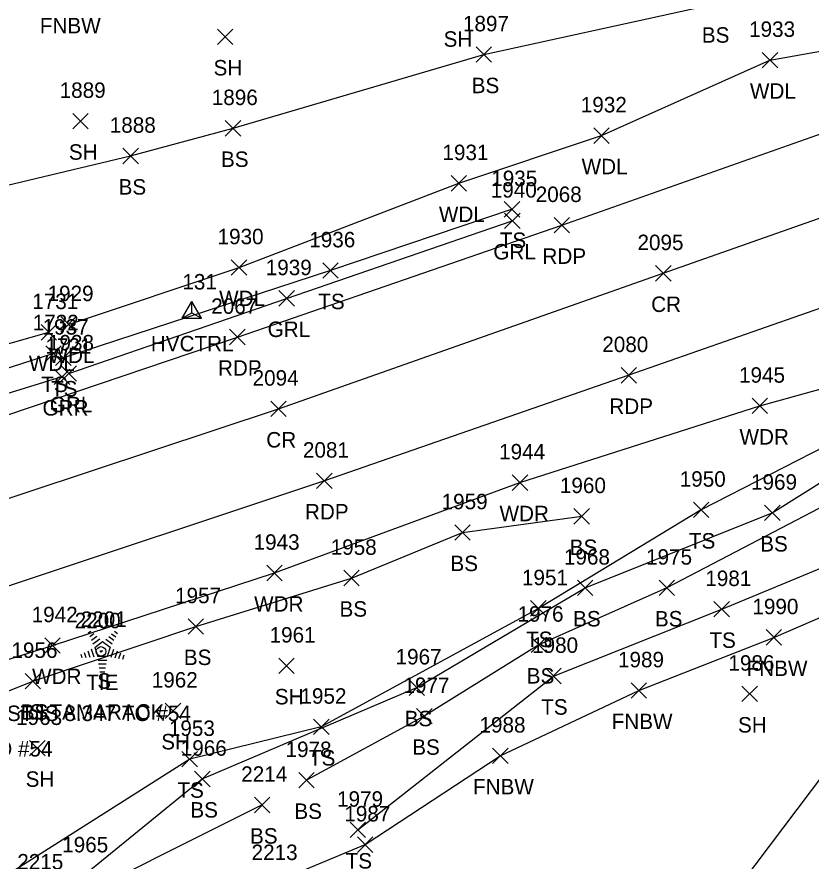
# Model space of a CAD drawing. Extents: x 1526508 to 1531550, y 369926 to 373082.
# Drawn here: x 1531231.6 to 1531334.3, y 370143.1 to 370252.3 of the extents above; entities that cross this region are included whole.
import ezdxf

# ---------------------------------------------------------------- set-up
doc = ezdxf.new("R2010")
doc.units = 0
for name, color, linetype in [('C_A', 7, 'Continuous'), ('C_C', 7, 'Continuous'), ('C_I', 7, 'Continuous'), ('CBP', 7, 'Continuous'), ('CPSM', 7, 'Continuous'), ('L_A', 7, 'Continuous'), ('L_C', 7, 'Continuous'), ('L_I', 7, 'Continuous'), ('L_TIC', 7, 'Continuous'), ('LAWA', 7, 'Continuous'), ('LELB', 7, 'Continuous'), ('LFNC', 7, 'Continuous'), ('LSOGP', 7, 'Continuous'), ('LTC', 7, 'Continuous'), ('P_A', 7, 'Continuous'), ('P_I', 7, 'Continuous'), ('P_TIC', 7, 'Continuous'), ('PET', 7, 'Continuous'), ('PRC', 7, 'Continuous'), ('R_A', 7, 'Continuous'), ('R_I', 7, 'Continuous'), ('R_TIC', 7, 'Continuous'), ('RGR', 7, 'Continuous')]:
    doc.layers.add(name, color=color, linetype=linetype)

msp = doc.modelspace()

# ---------------------------------------------------------------- linework, layer by layer
at = {"layer": 'CBP'}
for radius in [0.625, 0.0833]:
    msp.add_circle((1531242.44, 370170.23), radius, dxfattribs=at)
at = {"layer": 'CPSM'}
for p, q in [((1531252.93, 370213.33), (1531254.18, 370215.49)), ((1531255.43, 370213.33), (1531254.18, 370215.49)), ((1531254.18, 370214.05), (1531254.18, 370215.49)), ((1531252.93, 370213.33), (1531254.18, 370214.05)), ((1531254.18, 370214.05), (1531254.18, 370214.05)), ((1531254.18, 370214.05), (1531255.43, 370213.33)), ((1531252.93, 370213.33), (1531255.43, 370213.33))]:
    msp.add_line(p, q, dxfattribs=at)
at = {"layer": 'L_TIC'}
for points in [[(1531257.49, 370248.73), (1531259.49, 370250.73)], [(1531259.49, 370248.73), (1531257.49, 370250.73)], [(1531290.92, 370246.44), (1531292.92, 370248.44)], [(1531292.92, 370246.44), (1531290.92, 370248.44)], [(1531327.93, 370245.72), (1531329.93, 370247.72)], [(1531329.93, 370245.72), (1531327.93, 370247.72)], [(1531238.78, 370237.83), (1531240.78, 370239.83)], [(1531240.78, 370237.83), (1531238.78, 370239.83)], [(1531258.5, 370236.9), (1531260.5, 370238.9)], [(1531260.5, 370236.9), (1531258.5, 370238.9)], [(1531306.16, 370235.95), (1531308.16, 370237.95)], [(1531308.16, 370235.95), (1531306.16, 370237.95)], [(1531245.26, 370233.32), (1531247.26, 370235.32)], [(1531247.26, 370233.32), (1531245.26, 370235.32)], [(1531287.7, 370229.78), (1531289.7, 370231.78)], [(1531289.7, 370229.78), (1531287.7, 370231.78)], [(1531294.58, 370226.42), (1531296.58, 370228.42)], [(1531296.58, 370226.42), (1531294.58, 370228.42)], [(1531259.28, 370218.9), (1531261.28, 370220.9)], [(1531261.28, 370218.9), (1531259.28, 370220.9)], [(1531271.11, 370218.5), (1531273.11, 370220.5)], [(1531273.11, 370218.5), (1531271.11, 370220.5)], [(1531237.23, 370211.54), (1531239.23, 370213.54)], [(1531239.23, 370211.54), (1531237.23, 370213.54)], [(1531234.67, 370210.51), (1531236.67, 370212.51)], [(1531236.67, 370210.51), (1531234.67, 370212.51)], [(1531235.29, 370207.78), (1531237.29, 370209.78)], [(1531237.29, 370207.78), (1531235.29, 370209.78)], [(1531236.56, 370207.21), (1531238.56, 370209.21)], [(1531238.56, 370207.21), (1531236.56, 370209.21)], [(1531326.62, 370200.99), (1531328.62, 370202.99)], [(1531328.62, 370200.99), (1531326.62, 370202.99)], [(1531295.6, 370191.07), (1531297.6, 370193.07)], [(1531297.6, 370191.07), (1531295.6, 370193.07)], [(1531319.04, 370187.54), (1531321.04, 370189.54)], [(1531321.04, 370187.54), (1531319.04, 370189.54)], [(1531328.23, 370187.15), (1531330.23, 370189.15)], [(1531330.23, 370187.15), (1531328.23, 370189.15)], [(1531303.59, 370186.71), (1531305.59, 370188.71)], [(1531305.59, 370186.71), (1531303.59, 370188.71)], [(1531288.17, 370184.62), (1531290.17, 370186.62)], [(1531290.17, 370184.62), (1531288.17, 370186.62)], [(1531263.86, 370179.38), (1531265.86, 370181.38)], [(1531265.86, 370179.38), (1531263.86, 370181.38)], [(1531273.83, 370178.73), (1531275.83, 370180.73)], [(1531275.83, 370178.73), (1531273.83, 370180.73)], [(1531304.03, 370177.46), (1531306.03, 370179.46)], [(1531306.03, 370177.46), (1531304.03, 370179.46)], [(1531314.6, 370177.46), (1531316.6, 370179.46)], [(1531316.6, 370177.46), (1531314.6, 370179.46)], [(1531297.98, 370174.8), (1531299.98, 370176.8)], [(1531299.98, 370174.8), (1531297.98, 370176.8)], [(1531321.69, 370174.69), (1531323.69, 370176.69)], [(1531323.69, 370174.69), (1531321.69, 370176.69)], [(1531253.7, 370172.47), (1531255.7, 370174.47)], [(1531255.7, 370172.47), (1531253.7, 370174.47)], [(1531328.44, 370171.05), (1531330.44, 370173.05)], [(1531330.44, 370171.05), (1531328.44, 370173.05)], [(1531235.15, 370170.01), (1531237.15, 370172.01)], [(1531237.15, 370170.01), (1531235.15, 370172.01)], [(1531298.04, 370170.08), (1531300.04, 370172.08)], [(1531300.04, 370170.08), (1531298.04, 370172.08)], [(1531265.41, 370167.38), (1531267.41, 370169.38)], [(1531267.41, 370167.38), (1531265.41, 370169.38)], [(1531299.94, 370166.05), (1531301.94, 370168.05)], [(1531301.94, 370166.05), (1531299.94, 370168.05)], [(1531232.6, 370165.39), (1531234.6, 370167.39)], [(1531234.6, 370165.39), (1531232.6, 370167.39)], [(1531282.26, 370164.55), (1531284.26, 370166.55)], [(1531284.26, 370164.55), (1531282.26, 370166.55)], [(1531310.98, 370164.18), (1531312.98, 370166.18)], [(1531312.98, 370164.18), (1531310.98, 370166.18)], [(1531325.31, 370163.74), (1531327.31, 370165.74)], [(1531327.31, 370163.74), (1531325.31, 370165.74)], [(1531250.73, 370161.56), (1531252.73, 370163.56)], [(1531252.73, 370161.56), (1531250.73, 370163.56)], [(1531283.23, 370160.86), (1531285.23, 370162.86)], [(1531285.23, 370160.86), (1531283.23, 370162.86)], [(1531269.91, 370159.47), (1531271.91, 370161.47)], [(1531271.91, 370159.47), (1531269.91, 370161.47)], [(1531233.19, 370156.72), (1531235.19, 370158.72)], [(1531235.19, 370156.72), (1531233.19, 370158.72)], [(1531252.9, 370155.3), (1531254.9, 370157.3)], [(1531254.9, 370155.3), (1531252.9, 370157.3)], [(1531293.06, 370155.74), (1531295.06, 370157.74)], [(1531295.06, 370155.74), (1531293.06, 370157.74)], [(1531254.53, 370152.74), (1531256.53, 370154.74)], [(1531256.53, 370152.74), (1531254.53, 370154.74)], [(1531267.99, 370152.57), (1531269.99, 370154.57)], [(1531269.99, 370152.57), (1531267.99, 370154.57)], [(1531262.26, 370149.37), (1531264.26, 370151.37)], [(1531264.26, 370149.37), (1531262.26, 370151.37)], [(1531274.65, 370146.15), (1531276.65, 370148.15)], [(1531276.65, 370146.15), (1531274.65, 370148.15)], [(1531275.59, 370144.24), (1531277.59, 370146.24)], [(1531277.59, 370144.24), (1531275.59, 370146.24)]]:
    msp.add_lwpolyline(points, dxfattribs=at)
at = {"layer": 'LAWA'}
for points in [[(1531238.23, 370212.54), (1531260.28, 370219.9), (1531288.7, 370230.78), (1531307.16, 370236.95), (1531328.93, 370246.72), (1531350.71, 370250.57)], [(1531211.59, 370163.28), (1531236.15, 370171.01), (1531264.86, 370180.38), (1531296.6, 370192.07), (1531327.62, 370201.99), (1531350.93, 370208.46), (1531364.52, 370214)], [(1531159.07, 370187.01), (1531173.89, 370194.26), (1531191.12, 370197.26), (1531211.54, 370204.68), (1531235.67, 370211.51)]]:
    msp.add_lwpolyline(points, dxfattribs=at)
at = {"layer": 'LELB'}
for points in [[(1531144.65, 370206.06), (1531164.57, 370210.72), (1531180.3, 370218.31), (1531196.61, 370223.05), (1531216.18, 370227.2), (1531246.26, 370234.32), (1531259.5, 370237.9), (1531291.92, 370247.44), (1531321.67, 370253.97), (1531341.88, 370260.29), (1531377.42, 370272.37), (1531403.24, 370281.83), (1531425.1, 370287.02), (1531443.59, 370293.1), (1531470.33, 370300.31), (1531494.61, 370309.28), (1531517.9, 370316.82)], [(1531295.58, 370227.42), (1531272.11, 370219.5), (1531237.56, 370208.21)], [(1531365.84, 370210.96), (1531346.81, 370202.24), (1531320.04, 370188.54), (1531298.98, 370175.8), (1531270.91, 370160.47), (1531253.9, 370156.3), (1531223.1, 370136.77)], [(1531240.15, 370141.24), (1531255.53, 370153.74), (1531283.26, 370165.55), (1531305.03, 370178.46), (1531329.23, 370188.15), (1531348.16, 370200.01), (1531367.42, 370209.81)], [(1531236.29, 370208.78), (1531218.73, 370203.11), (1531203, 370197.34), (1531194.02, 370193.73)], [(1531369.65, 370204.02), (1531357.94, 370200.81), (1531337.22, 370189.77), (1531315.6, 370178.46), (1531299.04, 370171.08), (1531284.23, 370161.86), (1531268.99, 370153.57)], [(1531275.65, 370147.15), (1531300.94, 370167.05), (1531322.69, 370175.69), (1531354.73, 370189)], [(1531214.89, 370158.88), (1531233.6, 370166.39), (1531254.7, 370173.47), (1531274.83, 370179.73), (1531289.17, 370185.62), (1531304.59, 370187.71)], [(1531263.26, 370150.37), (1531234.42, 370135.95), (1531202.13, 370117.01), (1531177.7, 370099.03), (1531161.73, 370089.44), (1531148.84, 370085.31), (1531148.5, 370086.91)]]:
    msp.add_lwpolyline(points, dxfattribs=at)
at = {"layer": 'LFNC'}
for points in [[(1531276.59, 370145.24), (1531294.06, 370156.74), (1531311.98, 370165.18), (1531329.44, 370172.05), (1531342.78, 370177.81)], [(1531264.6, 370140.25), (1531276.59, 370145.24)]]:
    msp.add_lwpolyline(points, dxfattribs=at)
at = {"layer": 'LSOGP'}
msp.add_lwpolyline([(1531297.73, 370103.77), (1531345.31, 370166.81)], dxfattribs=at)
at = {"layer": 'LTC'}
for p, q in [((1531240.76, 370172.62), (1531241.12, 370172.87)), ((1531240.97, 370172.15), (1531241.5, 370172.54)), ((1531243.79, 370172.51), (1531244.34, 370172.11)), ((1531244.16, 370172.86), (1531244.58, 370172.55)), ((1531241.18, 370171.69), (1531241.89, 370172.2)), ((1531241.39, 370171.22), (1531242.27, 370171.86)), ((1531241.62, 370170.76), (1531242.63, 370171.5)), ((1531242.63, 370171.5), (1531243.62, 370170.77)), ((1531243.05, 370171.81), (1531243.86, 370171.22)), ((1531243.42, 370172.16), (1531244.1, 370171.67)), ((1531240.71, 370170.33), (1531240.98, 370169.49)), ((1531241.16, 370170.55), (1531241.49, 370169.53)), ((1531241.62, 370170.76), (1531242, 370169.57)), ((1531243.62, 370170.77), (1531243.23, 370169.57)), ((1531244.06, 370170.5), (1531243.72, 370169.46)), ((1531244.51, 370170.25), (1531244.22, 370169.37)), ((1531239.8, 370169.9), (1531239.95, 370169.43)), ((1531240.25, 370170.11), (1531240.46, 370169.46)), ((1531243.23, 370169.57), (1531242, 370169.57)), ((1531244.95, 370170), (1531244.71, 370169.27)), ((1531245.4, 370169.75), (1531245.21, 370169.18)), ((1531243.2, 370169.07), (1531242.05, 370169.07)), ((1531243.11, 370168.57), (1531242.12, 370168.57)), ((1531243.03, 370168.07), (1531242.2, 370168.07)), ((1531242.94, 370167.57), (1531242.27, 370167.57))]:
    msp.add_line(p, q, dxfattribs=at)
at = {"layer": 'P_TIC'}
for points in [[(1531301.03, 370224.36), (1531303.03, 370226.36)], [(1531303.03, 370224.36), (1531301.03, 370226.36)], [(1531314.14, 370218.14), (1531316.14, 370220.14)], [(1531316.14, 370218.14), (1531314.14, 370220.14)], [(1531259.06, 370209.9), (1531261.06, 370211.9)], [(1531261.06, 370209.9), (1531259.06, 370211.9)], [(1531309.67, 370204.95), (1531311.67, 370206.95)], [(1531311.67, 370204.95), (1531309.67, 370206.95)], [(1531264.37, 370200.61), (1531266.37, 370202.61)], [(1531266.37, 370200.61), (1531264.37, 370202.61)], [(1531270.31, 370191.3), (1531272.31, 370193.3)], [(1531272.31, 370191.3), (1531270.31, 370193.3)]]:
    msp.add_lwpolyline(points, dxfattribs=at)
at = {"layer": 'PET'}
for points in [[(1531036.19, 370150.91), (1531061.97, 370155.43), (1531104.8, 370164.58), (1531143.1, 370174.02), (1531180.11, 370184.91), (1531218.48, 370196.81), (1531260.06, 370210.9), (1531302.03, 370225.36), (1531352.57, 370243.2), (1531401.62, 370260.1), (1531448.12, 370277.05), (1531486.93, 370290.59), (1531531.91, 370306.21)], [(1531538.54, 370286.02), (1531506.28, 370274.48), (1531462.76, 370259.55), (1531429.61, 370248.08), (1531393.11, 370234.63), (1531350.62, 370219.92), (1531310.67, 370205.95), (1531271.31, 370192.3), (1531228.45, 370178.01), (1531188.4, 370165.28), (1531155.96, 370155.78), (1531116.2, 370145.37), (1531081.97, 370137.61), (1531057.06, 370132.93), (1531039.15, 370130.45)]]:
    msp.add_lwpolyline(points, dxfattribs=at)
at = {"layer": 'PRC'}
msp.add_lwpolyline([(1531037.76, 370140.53), (1531081.39, 370148.17), (1531130.61, 370160.04), (1531176.3, 370172.81), (1531216.72, 370185.49), (1531265.37, 370201.61), (1531315.14, 370219.14), (1531364.47, 370236.54), (1531403.01, 370250.24), (1531441.26, 370263.86), (1531484.78, 370279.08), (1531519.83, 370291.48), (1531535.78, 370296.89)], dxfattribs=at)
at = {"layer": 'R_TIC'}
for points in [[(1531294.61, 370224.93), (1531296.61, 370226.93)], [(1531296.61, 370224.93), (1531294.61, 370226.93)], [(1531265.43, 370214.9), (1531267.43, 370216.9)], [(1531267.43, 370214.9), (1531265.43, 370216.9)], [(1531236.38, 370204.74), (1531238.38, 370206.74)], [(1531238.38, 370204.74), (1531236.38, 370206.74)], [(1531237.27, 370205.17), (1531239.27, 370207.17)], [(1531239.27, 370205.17), (1531237.27, 370207.17)]]:
    msp.add_lwpolyline(points, dxfattribs=at)
at = {"layer": 'RGR'}
for points in [[(1531238.27, 370206.17), (1531266.43, 370215.9), (1531295.61, 370225.93)], [(1531237.38, 370205.74), (1531208.31, 370196.79), (1531193.99, 370191.5)]]:
    msp.add_lwpolyline(points, dxfattribs=at)

# ---------------------------------------------------------------- texts
at = {"layer": 'C_A'}
for s, p in [('HVCTRL', (1531248.87, 370209.05)), ('TIE', (1531240.52, 370165.23))]:
    msp.add_text(s, height=2, dxfattribs=at).set_placement(p)
at = {"layer": 'C_C'}
for s, p in [('TIE DIST IS 8.347 TO #54', (1531222.68, 370161.23)), ('TIE DIST IS 21.63 TO #54', (1531204.79, 370156.64))]:
    msp.add_text(s, height=2, dxfattribs=at).set_placement(p)
at = {"layer": 'C_I'}
for s, p in [('131', (1531252.95, 370217.05)), ('2200', (1531239.02, 370173.23))]:
    msp.add_text(s, height=2, dxfattribs=at).set_placement(p)
at = {"layer": 'L_A'}
for s, p in [('FNBW', (1531234.52, 370250.18)), ('SH', (1531286.73, 370248.44)), ('BS', (1531320.12, 370248.97)), ('SH', (1531256.98, 370244.73)), ('BS', (1531290.36, 370242.44)), ('WDL', (1531326.34, 370241.72)), ('SH', (1531238.27, 370233.83)), ('BS', (1531257.94, 370232.9)), ('WDL', (1531304.58, 370231.95)), ('BS', (1531244.7, 370229.32)), ('WDL', (1531286.12, 370225.78)), ('TS', (1531293.99, 370222.42)), ('WDL', (1531257.7, 370214.9)), ('TS', (1531270.52, 370214.5)), ('WDL', (1531235.64, 370207.54)), ('WDL', (1531233.09, 370206.51)), ('TS', (1531234.7, 370203.78)), ('TS', (1531235.97, 370203.21)), ('WDR', (1531324.99, 370196.99)), ('WDR', (1531293.96, 370187.07)), ('TS', (1531318.45, 370183.54)), ('BS', (1531303.04, 370182.71)), ('BS', (1531327.67, 370183.15)), ('BS', (1531287.61, 370180.62)), ('WDR', (1531262.22, 370175.38)), ('BS', (1531273.27, 370174.73)), ('BS', (1531303.47, 370173.46)), ('BS', (1531314.05, 370173.46)), ('TS', (1531297.39, 370170.8)), ('TS', (1531321.1, 370170.69)), ('BS', (1531253.14, 370168.47)), ('WDR', (1531233.51, 370166.01)), ('BS', (1531297.48, 370166.08)), ('FNBW', (1531325.91, 370167.05)), ('S', (1531241.95, 370165.41)), ('SH', (1531264.9, 370163.38)), ('TS', (1531299.35, 370162.05)), ('BS', (1531232.04, 370161.39)), ('BS', (1531281.7, 370160.55)), ('FNBW', (1531308.46, 370160.18)), ('SH', (1531324.8, 370159.74)), ('SH', (1531250.22, 370157.56)), ('BS', (1531282.67, 370156.86)), ('TS', (1531269.32, 370155.47)), ('SH', (1531232.68, 370152.72)), ('TS', (1531252.31, 370151.3)), ('FNBW', (1531290.53, 370151.74)), ('BS', (1531253.98, 370148.74)), ('BS', (1531267.43, 370148.57)), ('BS', (1531261.7, 370145.37)), ('TS', (1531274.06, 370142.15))]:
    msp.add_text(s, height=2, dxfattribs=at).set_placement(p)
at = {"layer": 'L_C'}
msp.add_text('S TAMARACK', height=2, dxfattribs=at).set_placement((1531233.24, 370161.41))
at = {"layer": 'L_I'}
for s, p in [('1897', (1531289.23, 370250.44)), ('1933', (1531326.23, 370249.72)), ('1889', (1531237.08, 370241.83)), ('1896', (1531256.75, 370240.9)), ('1932', (1531304.47, 370239.95)), ('1888', (1531243.56, 370237.32)), ('1931', (1531286.58, 370233.78)), ('1935', (1531292.89, 370230.42)), ('1930', (1531257.5, 370222.9)), ('1936', (1531269.36, 370222.5)), ('1929', (1531235.52, 370215.54)), ('1731', (1531233.54, 370214.51)), ('1732', (1531233.6, 370211.78)), ('1937', (1531234.87, 370211.21)), ('1945', (1531324.93, 370204.99)), ('1944', (1531293.91, 370195.07)), ('1950', (1531317.26, 370191.54)), ('1969', (1531326.48, 370191.15)), ('1960', (1531301.77, 370190.71)), ('1959', (1531286.47, 370188.62)), ('1943', (1531262.16, 370183.38)), ('1958', (1531272.13, 370182.73)), ('1968', (1531302.29, 370181.46)), ('1975', (1531312.91, 370181.46)), ('1951', (1531296.86, 370178.8)), ('1981', (1531320.57, 370178.69)), ('1957', (1531252, 370176.47)), ('1990', (1531326.66, 370175.05)), ('1942', (1531233.46, 370174.01)), ('1976', (1531296.29, 370174.08)), ('2201', (1531239.8, 370173.41)), ('1961', (1531264.23, 370171.38)), ('1956', (1531230.85, 370169.39)), ('1980', (1531298.17, 370170.05)), ('1967', (1531280.52, 370168.55)), ('1989', (1531309.28, 370168.18)), ('1986', (1531323.56, 370167.74)), ('1962', (1531248.99, 370165.56)), ('1977', (1531281.54, 370164.86)), ('1952', (1531268.22, 370163.47)), ('1963', (1531231.45, 370160.72)), ('1988', (1531291.37, 370159.74)), ('1953', (1531251.2, 370159.3)), ('1966', (1531252.74, 370156.74)), ('1978', (1531266.29, 370156.57)), ('2214', (1531260.56, 370153.37)), ('1979', (1531272.95, 370150.15)), ('1987', (1531273.89, 370148.24)), ('1965', (1531237.41, 370144.24)), ('2213', (1531261.9, 370143.25)), ('2215', (1531231.6, 370142.03))]:
    msp.add_text(s, height=2, dxfattribs=at).set_placement(p)
at = {"layer": 'LTC'}
msp.add_text('.', height=1.04, rotation=270, dxfattribs=at).set_placement((1531242.51, 370170.51))
at = {"layer": 'P_A'}
for s, p in [('RDP', (1531299.51, 370220.36)), ('CR', (1531313.57, 370214.14)), ('RDP', (1531257.55, 370205.9)), ('RDP', (1531308.16, 370200.95)), ('CR', (1531263.8, 370196.61)), ('RDP', (1531268.8, 370187.3))]:
    msp.add_text(s, height=2, dxfattribs=at).set_placement(p)
at = {"layer": 'P_I'}
for s, p in [('2068', (1531298.64, 370228.36)), ('2095', (1531311.8, 370222.14)), ('2067', (1531256.68, 370213.9)), ('2080', (1531307.25, 370208.95)), ('2094', (1531262.03, 370204.61)), ('2081', (1531268.54, 370195.3))]:
    msp.add_text(s, height=2, dxfattribs=at).set_placement(p)
at = {"layer": 'R_A'}
for s, p in [('GRL', (1531293.16, 370220.93)), ('GRL', (1531263.98, 370210.9)), ('GRL', (1531235.81, 370201.17)), ('GRR', (1531234.86, 370200.74))]:
    msp.add_text(s, height=2, dxfattribs=at).set_placement(p)
at = {"layer": 'R_I'}
for s, p in [('1940', (1531292.83, 370228.93)), ('1939', (1531263.73, 370218.9)), ('1721', (1531235.25, 370208.74)), ('1938', (1531235.57, 370209.17))]:
    msp.add_text(s, height=2, dxfattribs=at).set_placement(p)

doc.saveas('drawing.dxf')
